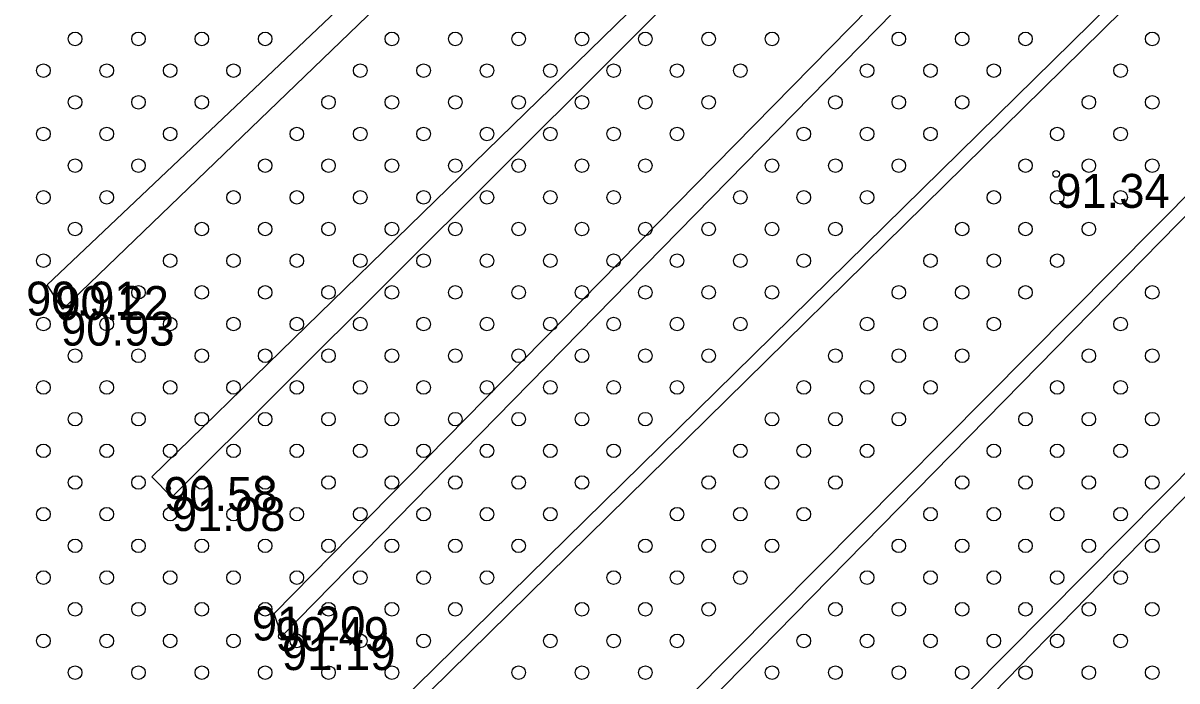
# Model space of a CAD drawing. Extents: x 316000 to 728450, y 314368 to 726000.
# Drawn here: x 725638.8 to 725766.2, y 315450.6 to 315523.2 of the extents above; entities that cross this region are included whole.
import ezdxf

# ---------------------------------------------------------------- set-up
doc = ezdxf.new("R2010")
doc.units = 0
for name, color, linetype in [('HIDG_ELEM_####_####_#', 7, 'Continuous'), ('HIDG_GRAV_####_####_#', 7, 'Continuous'), ('RELJ_AATZ_####_TKST_#', 7, 'Continuous'), ('RELJ_ELEM_####_####_#', 7, 'Continuous'), ('RELJ_NOGA_####_####_#', 7, 'Continuous'), ('TERT_ELEM_####_####_#', 7, 'Continuous')]:
    doc.layers.add(name, color=color, linetype=linetype)

msp = doc.modelspace()

# ---------------------------------------------------------------- linework, layer by layer
at = {"layer": 'HIDG_ELEM_####_####_#'}
for centre in [(725642.72, 315493.24), (725654.81, 315471.85), (725667.28, 315457.25)]:
    msp.add_circle(centre, 0.225, dxfattribs=at)
at = {"layer": 'HIDG_GRAV_####_####_#'}
for points in [[(725748.97, 315596.21), (725751.01, 315595.51), (725643.15, 315491.63), (725641.41, 315494.34), (725748.97, 315596.21)], [(725762.52, 315579.88), (725763.92, 315579.31), (725655.19, 315470.89), (725652.98, 315473.11), (725762.52, 315579.88)], [(725774.6, 315568.07), (725776.9, 315567.31), (725667.35, 315455.53), (725666.51, 315458.03), (725774.6, 315568.07)], [(725789.82, 315555.77), (725790.78, 315554.71), (725668.4, 315434.39), (725667.72, 315435.8), (725789.82, 315555.77)], [(725806.05, 315543.31), (725806.83, 315542.39), (725671.92, 315404.85), (725670.3, 315406.43), (725806.05, 315543.31)], [(725811.36, 315518.13), (725812.41, 315517.33), (725689.87, 315391.76), (725687.94, 315393.64), (725811.36, 315518.13)]]:
    msp.add_lwpolyline(points, dxfattribs=at)
msp.add_spline([(725741.16, 315628.11), (725732.01, 315633.48), (725729.37, 315630.94), (725612.67, 315527.51), (725555.21, 315474.31)], degree=3, dxfattribs=at)
at = {"layer": 'RELJ_ELEM_####_####_#'}
for centre in [(725752.89, 315506.59), (725667.35, 315455.53)]:
    msp.add_circle(centre, 0.375, dxfattribs=at)
at = {"layer": 'RELJ_NOGA_####_####_#'}
for points in [[(726259.12, 315084.51), (726262.72, 315089.26), (726261.56, 315090.84), (726260.2, 315092.42), (726257.29, 315095.53), (726218.91, 315136.38), (726180.31, 315176.84), (726128.67, 315229.97), (726063.7, 315298.11), (725999.9, 315366.09), (725937.21, 315432.09), (725876.35, 315495.23), (725810.58, 315563.08), (725744.7, 315632.91)], [(725740.86, 315626.98), (725805.54, 315558.12), (725870.39, 315491.15), (725932.8, 315426.8), (725994.98, 315360.84), (726059.66, 315292.12), (726075.75, 315275.46), (726092.08, 315259.04), (726108.47, 315242.67), (726124.69, 315226.14), (726193.27, 315154.03), (726250.06, 315092.6), (726256.32, 315085.83), (726258.82, 315084.29), (726259.12, 315084.51)]]:
    msp.add_spline(points, degree=3, dxfattribs=at)
at = {"layer": 'TERT_ELEM_####_####_#'}
for centre in [(725644.5, 315521.5), (725651.5, 315521.5), (725658.5, 315521.5), (725665.5, 315521.5), (725679.5, 315521.5), (725686.5, 315521.5), (725693.5, 315521.5), (725700.5, 315521.5), (725707.5, 315521.5), (725714.5, 315521.5), (725721.5, 315521.5), (725735.5, 315521.5), (725742.5, 315521.5), (725749.5, 315521.5), (725763.5, 315521.5), (725641, 315518), (725648, 315518), (725655, 315518), (725662, 315518), (725676, 315518), (725683, 315518), (725690, 315518), (725697, 315518), (725704, 315518), (725711, 315518), (725718, 315518), (725732, 315518), (725739, 315518), (725746, 315518), (725760, 315518), (725644.5, 315514.5), (725651.5, 315514.5), (725658.5, 315514.5), (725672.5, 315514.5), (725679.5, 315514.5), (725686.5, 315514.5), (725693.5, 315514.5), (725700.5, 315514.5), (725707.5, 315514.5), (725714.5, 315514.5), (725728.5, 315514.5), (725735.5, 315514.5), (725742.5, 315514.5), (725756.5, 315514.5), (725763.5, 315514.5), (725641, 315511), (725648, 315511), (725655, 315511), (725669, 315511), (725676, 315511), (725683, 315511), (725690, 315511), (725697, 315511), (725704, 315511), (725711, 315511), (725725, 315511), (725732, 315511), (725739, 315511), (725753, 315511), (725760, 315511), (725644.5, 315507.5), (725651.5, 315507.5), (725665.5, 315507.5), (725672.5, 315507.5), (725679.5, 315507.5), (725686.5, 315507.5), (725693.5, 315507.5), (725700.5, 315507.5), (725707.5, 315507.5), (725721.5, 315507.5), (725728.5, 315507.5), (725735.5, 315507.5), (725749.5, 315507.5), (725756.5, 315507.5), (725763.5, 315507.5), (725641, 315504), (725648, 315504), (725662, 315504), (725669, 315504), (725676, 315504), (725683, 315504), (725690, 315504), (725697, 315504), (725704, 315504), (725718, 315504), (725725, 315504), (725732, 315504), (725746, 315504), (725753, 315504), (725760, 315504), (725644.5, 315500.5), (725658.5, 315500.5), (725665.5, 315500.5), (725672.5, 315500.5), (725679.5, 315500.5), (725686.5, 315500.5), (725693.5, 315500.5), (725700.5, 315500.5), (725707.5, 315500.5), (725714.5, 315500.5), (725721.5, 315500.5), (725728.5, 315500.5), (725742.5, 315500.5), (725749.5, 315500.5), (725756.5, 315500.5), (725641, 315497), (725655, 315497), (725662, 315497), (725669, 315497), (725676, 315497), (725683, 315497), (725690, 315497), (725697, 315497), (725704, 315497), (725711, 315497), (725718, 315497), (725725, 315497), (725739, 315497), (725746, 315497), (725753, 315497), (725651.5, 315493.5), (725658.5, 315493.5), (725665.5, 315493.5), (725672.5, 315493.5), (725679.5, 315493.5), (725686.5, 315493.5), (725693.5, 315493.5), (725700.5, 315493.5), (725707.5, 315493.5), (725714.5, 315493.5), (725721.5, 315493.5), (725735.5, 315493.5), (725742.5, 315493.5), (725749.5, 315493.5), (725763.5, 315493.5), (725641, 315490), (725648, 315490), (725655, 315490), (725662, 315490), (725669, 315490), (725676, 315490), (725683, 315490), (725690, 315490), (725697, 315490), (725704, 315490), (725711, 315490), (725718, 315490), (725732, 315490), (725739, 315490), (725746, 315490), (725760, 315490), (725644.5, 315486.5), (725651.5, 315486.5), (725658.5, 315486.5), (725665.5, 315486.5), (725672.5, 315486.5), (725679.5, 315486.5), (725686.5, 315486.5), (725693.5, 315486.5), (725700.5, 315486.5), (725707.5, 315486.5), (725714.5, 315486.5), (725728.5, 315486.5), (725735.5, 315486.5), (725742.5, 315486.5), (725756.5, 315486.5), (725763.5, 315486.5), (725641, 315483), (725648, 315483), (725655, 315483), (725662, 315483), (725669, 315483), (725676, 315483), (725683, 315483), (725690, 315483), (725697, 315483), (725704, 315483), (725711, 315483), (725725, 315483), (725732, 315483), (725739, 315483), (725753, 315483), (725760, 315483), (725644.5, 315479.5), (725651.5, 315479.5), (725658.5, 315479.5), (725665.5, 315479.5), (725672.5, 315479.5), (725679.5, 315479.5), (725686.5, 315479.5), (725693.5, 315479.5), (725700.5, 315479.5), (725707.5, 315479.5), (725721.5, 315479.5), (725728.5, 315479.5), (725735.5, 315479.5), (725749.5, 315479.5), (725756.5, 315479.5), (725763.5, 315479.5), (725641, 315476), (725648, 315476), (725655, 315476), (725662, 315476), (725669, 315476), (725676, 315476), (725683, 315476), (725690, 315476), (725697, 315476), (725704, 315476), (725718, 315476), (725725, 315476), (725732, 315476), (725746, 315476), (725753, 315476), (725760, 315476), (725644.5, 315472.5), (725651.5, 315472.5), (725658.5, 315472.5), (725665.5, 315472.5), (725672.5, 315472.5), (725679.5, 315472.5), (725686.5, 315472.5), (725693.5, 315472.5), (725700.5, 315472.5), (725714.5, 315472.5), (725721.5, 315472.5), (725728.5, 315472.5), (725742.5, 315472.5), (725749.5, 315472.5), (725756.5, 315472.5), (725763.5, 315472.5), (725641, 315469), (725648, 315469), (725655, 315469), (725662, 315469), (725669, 315469), (725676, 315469), (725683, 315469), (725690, 315469), (725697, 315469), (725711, 315469), (725718, 315469), (725725, 315469), (725739, 315469), (725746, 315469), (725753, 315469), (725760, 315469), (725644.5, 315465.5), (725651.5, 315465.5), (725658.5, 315465.5), (725665.5, 315465.5), (725672.5, 315465.5), (725679.5, 315465.5), (725686.5, 315465.5), (725693.5, 315465.5), (725707.5, 315465.5), (725714.5, 315465.5), (725721.5, 315465.5), (725735.5, 315465.5), (725742.5, 315465.5), (725749.5, 315465.5), (725756.5, 315465.5), (725763.5, 315465.5), (725641, 315462), (725648, 315462), (725655, 315462), (725662, 315462), (725669, 315462), (725676, 315462), (725683, 315462), (725690, 315462), (725704, 315462), (725711, 315462), (725718, 315462), (725732, 315462), (725739, 315462), (725746, 315462), (725753, 315462), (725760, 315462), (725644.5, 315458.5), (725651.5, 315458.5), (725658.5, 315458.5), (725665.5, 315458.5), (725672.5, 315458.5), (725679.5, 315458.5), (725686.5, 315458.5), (725700.5, 315458.5), (725707.5, 315458.5), (725714.5, 315458.5), (725728.5, 315458.5), (725735.5, 315458.5), (725742.5, 315458.5), (725749.5, 315458.5), (725756.5, 315458.5), (725763.5, 315458.5), (725641, 315455), (725648, 315455), (725655, 315455), (725662, 315455), (725669, 315455), (725676, 315455), (725683, 315455), (725697, 315455), (725704, 315455), (725711, 315455), (725725, 315455), (725732, 315455), (725739, 315455), (725746, 315455), (725753, 315455), (725760, 315455), (725644.5, 315451.5), (725651.5, 315451.5), (725658.5, 315451.5), (725665.5, 315451.5), (725672.5, 315451.5), (725679.5, 315451.5), (725693.5, 315451.5), (725700.5, 315451.5), (725707.5, 315451.5), (725721.5, 315451.5), (725728.5, 315451.5), (725735.5, 315451.5), (725742.5, 315451.5), (725749.5, 315451.5), (725756.5, 315451.5), (725763.5, 315451.5)]:
    msp.add_circle(centre, 0.75, dxfattribs=at)

# ---------------------------------------------------------------- texts
at = {"layer": 'RELJ_AATZ_####_TKST_#'}
for s, p in [('91.34', (725752.89, 315502.84)), ('90.91', (725639.08, 315490.94)), ('90.22', (725642.31, 315490.45)), ('90.93', (725642.94, 315487.62)), ('90.58', (725654.32, 315469.36)), ('91.08', (725655.19, 315467.14)), ('91.20', (725664.03, 315455.05)), ('90.49', (725666.63, 315453.88)), ('91.19', (725667.35, 315451.78))]:
    msp.add_text(s, height=3.75, dxfattribs=at).set_placement(p)

doc.saveas('drawing.dxf')
